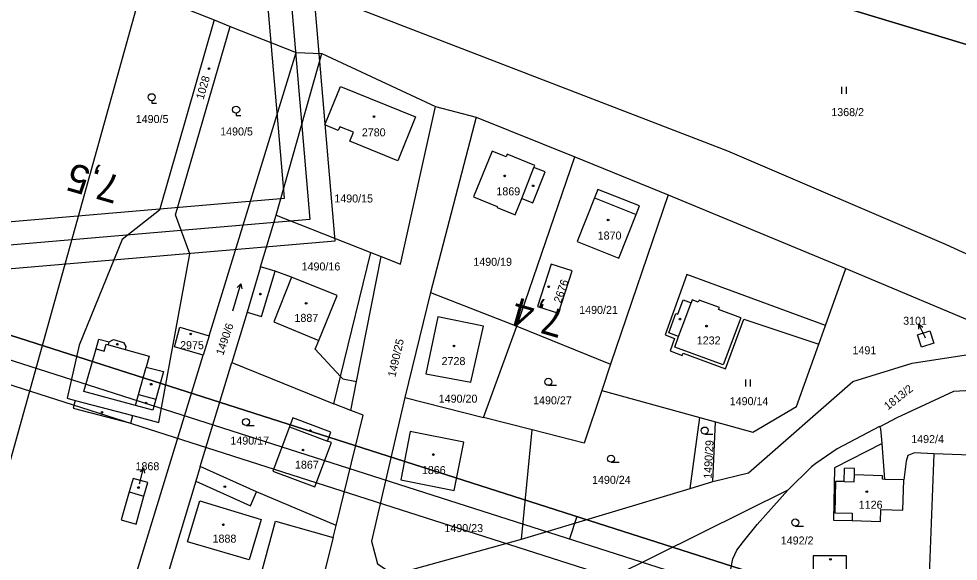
# Model space of a CAD drawing. Extents: x -779330 to -774454, y -1144748 to -1142831.
# Drawn here: x -777612.9 to -777413.3, y -1143849.7 to -1143734.5 of the extents above; entities that cross this region are included whole.
import ezdxf

# ---------------------------------------------------------------- set-up
doc = ezdxf.new("R2010")
doc.units = 0
for name, color, linetype in [('Hranice parcel', 7, 'Continuous'), ('Parcelní čísla', 7, 'Continuous'), ('Pop  PČ popisy', 7, 'Continuous'), ('SŽDC', 7, 'Continuous'), ('Vnitřní kresba', 7, 'Continuous'), ('Vrstva 1', 7, 'Continuous'), ('Vrstva 53', 7, 'Continuous'), ('Vrstva 7', 7, 'Continuous'), ('Značky budov', 7, 'Continuous'), ('Značky kultur', 7, 'Continuous')]:
    doc.layers.add(name, color=color, linetype=linetype)

msp = doc.modelspace()

# ---------------------------------------------------------------- linework, layer by layer
at = {"layer": 'Hranice parcel'}
for p, q in [((-777586.96, -1143728.55), (-777628.63, -1143877.96)), ((-777586.96, -1143728.55), (-777571.45, -1143734.73)), ((-777571.45, -1143734.73), (-777568.02, -1143736.1)), ((-777568.02, -1143736.1), (-777554, -1143741.68)), ((-777572.48, -1143801.82), (-777554, -1143741.68)), ((-777558.25, -1143776.21), (-777548.54, -1143741.84)), ((-777554, -1143741.68), (-777548.54, -1143741.84)), ((-777548.54, -1143741.84), (-777524.39, -1143753.1)), ((-777524.39, -1143753.1), (-777515.73, -1143755.37)), ((-777515.73, -1143755.37), (-777525.48, -1143792.66)), ((-777515.73, -1143755.37), (-777494.83, -1143763.84)), ((-777507.11, -1143799.78), (-777494.83, -1143763.84)), ((-777494.83, -1143763.84), (-777474.95, -1143771.88)), ((-777474.95, -1143771.88), (-777487.19, -1143807.86)), ((-777474.95, -1143771.88), (-777437.2, -1143787.51)), ((-777561.56, -1143787.19), (-777558.25, -1143776.21)), ((-777558.25, -1143776.21), (-777538.11, -1143784.15)), ((-777544.59, -1143810.44), (-777538.11, -1143784.15)), ((-777441.55, -1143799.67), (-777437.2, -1143787.51)), ((-777525.48, -1143792.66), (-777530.89, -1143814.94)), ((-777525.48, -1143792.66), (-777507.11, -1143799.78)), ((-777579.84, -1143804.2), (-777578.68, -1143800.03)), ((-777578.68, -1143800.03), (-777572.48, -1143801.82)), ((-777514.23, -1143819.18), (-777507.11, -1143799.78)), ((-777507.11, -1143799.78), (-777487.19, -1143807.86)), ((-777442.96, -1143803.61), (-777441.55, -1143799.67)), ((-777572.48, -1143801.82), (-777573.74, -1143805.93)), ((-777573.74, -1143805.93), (-777579.84, -1143804.2)), ((-777592.84, -1143868.11), (-777573.74, -1143805.93)), ((-777574.4, -1143829.61), (-777567.68, -1143807.53)), ((-777567.68, -1143807.53), (-777546.02, -1143816.25)), ((-777487.19, -1143807.86), (-777489.08, -1143813.43)), ((-777546.02, -1143816.25), (-777544.59, -1143810.44)), ((-777489.08, -1143813.43), (-777468.25, -1143819.2)), ((-777530.89, -1143814.94), (-777514.23, -1143819.18)), ((-777503.88, -1143821.81), (-777514.23, -1143819.18)), ((-777470.29, -1143834.25), (-777468.25, -1143819.2)), ((-777468.25, -1143819.2), (-777464.88, -1143820.14)), ((-777465.49, -1143832.81), (-777464.88, -1143820.14)), ((-777506.15, -1143845.05), (-777503.88, -1143821.81)), ((-777429.76, -1143821.62), (-777430, -1143821.16)), ((-777429.52, -1143824.74), (-777429.76, -1143821.62)), ((-777418.55, -1143826.88), (-777419.52, -1143852.7)), ((-777408.15, -1143827.26), (-777418.55, -1143826.88)), ((-777506.15, -1143845.05), (-777470.29, -1143834.25)), ((-777470.29, -1143834.25), (-777465.49, -1143832.81)), ((-777449.55, -1143834.59), (-777486.78, -1143853.07)), ((-777546.16, -1143844.71), (-777545.52, -1143842.15)), ((-777533.28, -1143852.53), (-777506.15, -1143845.05))]:
    msp.add_line(p, q, dxfattribs=at)
for points in [[(-777358.14, -1143760.61), (-777362.08, -1143759.74), (-777364.95, -1143754.01), (-777547.63, -1143698.79)], [(-777375.94, -1143800.75), (-777415.86, -1143782.49), (-777462.27, -1143762.62), (-777556.08, -1143726.43)], [(-777571.45, -1143734.73), (-777583.04, -1143775.14), (-777590.98, -1143781.34), (-777600.08, -1143803.81), (-777602.62, -1143815.11), (-777600.92, -1143815.55), (-777601.35, -1143817.2), (-777589.15, -1143820.42), (-777588.69, -1143818.74), (-777583.15, -1143820.25), (-777576.59, -1143784.44), (-777579.64, -1143776.1), (-777568.02, -1143736.1)], [(-777542.62, -1143760.45), (-777541.85, -1143758.59), (-777544.73, -1143757.41), (-777545.07, -1143758.22), (-777547.92, -1143757.03), (-777544.58, -1143748.84), (-777528.63, -1143755.28), (-777532.39, -1143764.63), (-777542.62, -1143760.45)], [(-777538.11, -1143784.15), (-777535.92, -1143785.01), (-777531.8, -1143786.63), (-777524.39, -1143753.1)], [(-777509.41, -1143763.79), (-777512.38, -1143762.59), (-777516.33, -1143772.28), (-777511.29, -1143774.33), (-777511.29, -1143774.58), (-777507.44, -1143776.1), (-777506.08, -1143772.67), (-777503.74, -1143773.61), (-777501.12, -1143767.03), (-777503.49, -1143766.09), (-777503.3, -1143765.62), (-777509.19, -1143763.24), (-777509.41, -1143763.79)], [(-777494.32, -1143781.82), (-777485.45, -1143785.36), (-777481.75, -1143776.05), (-777481.04, -1143774.24), (-777489.89, -1143770.75), (-777490.61, -1143772.54), (-777494.32, -1143781.82)], [(-777561.56, -1143787.19), (-777564.44, -1143796.78), (-777567.68, -1143807.53)], [(-777544.59, -1143810.44), (-777549.94, -1143804.7), (-777549.16, -1143802.8), (-777545.26, -1143793.28), (-777554.99, -1143789.4), (-777558.44, -1143788.13), (-777561.56, -1143787.19)], [(-777498.3, -1143797.05), (-777495.36, -1143788), (-777499.84, -1143786.63), (-777502.7, -1143795.62), (-777498.3, -1143797.05)], [(-777437.2, -1143787.51), (-777405.54, -1143800.83), (-777387.68, -1143807.89)], [(-777441.55, -1143799.67), (-777471.01, -1143788.8), (-777475.63, -1143801.6), (-777473.61, -1143802.41), (-777474.56, -1143805), (-777471.98, -1143806.02), (-777471.78, -1143805.5), (-777462.81, -1143808.82), (-777458.9, -1143798.28), (-777442.96, -1143803.61)], [(-777514.2, -1143799.8), (-777523.92, -1143797.78), (-777526.42, -1143809.9), (-777516.86, -1143811.71), (-777514.2, -1143799.8)], [(-777419.39, -1143800.8), (-777418.56, -1143803.42), (-777421.16, -1143804.21), (-777421.98, -1143801.63), (-777419.39, -1143800.8)], [(-777464.88, -1143820.14), (-777456.98, -1143822.28), (-777447.69, -1143816.85), (-777442.96, -1143803.61)], [(-777465.49, -1143832.81), (-777457.92, -1143830.94), (-777435.72, -1143811.54), (-777423.12, -1143807.62), (-777410.71, -1143805.75), (-777400, -1143806.27), (-777387.68, -1143807.89)], [(-777489.08, -1143813.43), (-777492.83, -1143824.62), (-777503.88, -1143821.81)], [(-777410.51, -1143813.42), (-777414.33, -1143813.66), (-777426.36, -1143819.29), (-777430, -1143821.16)], [(-777545.52, -1143842.15), (-777539.77, -1143818.66), (-777542.4, -1143817.71), (-777546.02, -1143816.25)], [(-777530.89, -1143814.94), (-777537.99, -1143845.48), (-777536.71, -1143850.29), (-777533.28, -1143852.53)], [(-777547.35, -1143824.19), (-777546.65, -1143822.31), (-777554.72, -1143819.29), (-777555.42, -1143821.17), (-777558.97, -1143830.56), (-777550.02, -1143833.94), (-777546.49, -1143824.51), (-777547.35, -1143824.19)], [(-777518.36, -1143824.44), (-777529.79, -1143822.14), (-777531.78, -1143832.46), (-777520.42, -1143834.72), (-777518.36, -1143824.44)], [(-777430, -1143821.16), (-777430.05, -1143821.07), (-777439.06, -1143825.81), (-777443.57, -1143828.99), (-777444.5, -1143829.67), (-777449.55, -1143834.59)], [(-777429.52, -1143824.74), (-777439.62, -1143829.91), (-777439.81, -1143840.98), (-777435.91, -1143841.04), (-777429.86, -1143841.27), (-777429.76, -1143838.71), (-777425.13, -1143838.85), (-777424.9, -1143832.45)], [(-777424.9, -1143832.45), (-777428.95, -1143832.33), (-777429.52, -1143824.74)], [(-777418.55, -1143826.88), (-777422.63, -1143826.67), (-777424.04, -1143827.28), (-777424.38, -1143828.48), (-777424.9, -1143832.45)], [(-777574.4, -1143829.61), (-777575.32, -1143832.68), (-777580.95, -1143851.46)], [(-777545.52, -1143842.15), (-777562.42, -1143835.01), (-777574.4, -1143829.61)], [(-777588.63, -1143832.11), (-777589.47, -1143835), (-777591.16, -1143840.91), (-777588.02, -1143841.81), (-777586.33, -1143835.89), (-777585.51, -1143833.01), (-777588.63, -1143832.11)], [(-777444.18, -1143852.13), (-777461.74, -1143851.77), (-777461.25, -1143849.21), (-777460.37, -1143847.4), (-777458.98, -1143845.51), (-777456.06, -1143841.9), (-777449.55, -1143834.59)], [(-777563.57, -1143860.33), (-777558.4, -1143841.22), (-777546.16, -1143844.71)], [(-777546.16, -1143844.71), (-777548.69, -1143854.82), (-777551.16, -1143857.13)], [(-777437.09, -1143852.27), (-777437.07, -1143848.56), (-777444.17, -1143848.54), (-777444.18, -1143852.13)]]:
    msp.add_lwpolyline(points, dxfattribs=at)
at = {"layer": 'Pop  PČ popisy'}
for p, q in [((-777421.78, -1143799.3), (-777421.79, -1143800.42)), ((-777420.46, -1143802), (-777421.78, -1143799.3)), ((-777421.78, -1143799.3), (-777420.89, -1143799.98)), ((-777420.31, -1143802.32), (-777420.46, -1143802)), ((-777587.17, -1143832.8), (-777586.44, -1143829.89)), ((-777586.44, -1143829.89), (-777587.17, -1143830.74)), ((-777586.44, -1143829.89), (-777586.2, -1143830.98)), ((-777587.29, -1143833.28), (-777587.17, -1143832.8))]:
    msp.add_line(p, q, dxfattribs=at)
at = {"layer": 'SŽDC'}
msp.add_lwpolyline([(-777622.38, -1143677.44), (-777550.6, -1143697.9), (-777547.63, -1143698.79), (-777364.95, -1143754.01), (-777362.08, -1143759.74), (-777358.14, -1143760.61), (-777354.56, -1143760.13), (-777348.72, -1143768.82), (-777340.59, -1143770.61)], dxfattribs=at)
at = {"layer": 'Vnitřní kresba'}
for p, q in [((-777506.08, -1143772.67), (-777503.49, -1143766.09)), ((-777490.61, -1143772.54), (-777481.75, -1143776.05)), ((-777541.16, -1143811.54), (-777535.92, -1143785.01)), ((-777561.33, -1143797.71), (-777558.44, -1143788.13)), ((-777554.99, -1143789.4), (-777558.75, -1143798.87)), ((-777472.93, -1143797.23), (-777471.79, -1143794.16)), ((-777471.79, -1143794.16), (-777470.07, -1143794.8)), ((-777469.84, -1143794.17), (-777470.07, -1143794.8)), ((-777468.56, -1143794.65), (-777469.84, -1143794.17)), ((-777468.4, -1143794.23), (-777468.56, -1143794.65)), ((-777464.08, -1143795.85), (-777468.4, -1143794.23)), ((-777471.21, -1143797.86), (-777470.07, -1143794.8)), ((-777464.24, -1143796.27), (-777464.08, -1143795.85)), ((-777459.56, -1143798.03), (-777464.24, -1143796.27)), ((-777564.44, -1143796.78), (-777561.33, -1143797.71)), ((-777474.81, -1143801.17), (-777473.33, -1143797.08)), ((-777473.33, -1143797.08), (-777472.93, -1143797.23)), ((-777472.78, -1143801.97), (-777471.21, -1143797.86)), ((-777459.56, -1143798.03), (-777463.27, -1143808.03)), ((-777558.75, -1143798.87), (-777549.16, -1143802.8)), ((-777472.78, -1143801.97), (-777474.81, -1143801.17)), ((-777473.56, -1143804.21), (-777472.78, -1143801.97)), ((-777596.52, -1143804.59), (-777595.93, -1143802.51)), ((-777595.93, -1143802.51), (-777593.7, -1143803.14)), ((-777594.8, -1143805.08), (-777594.37, -1143803.58)), ((-777594.37, -1143803.58), (-777593.86, -1143803.72)), ((-777593.86, -1143803.72), (-777593.7, -1143803.14)), ((-777593.86, -1143803.72), (-777590.36, -1143804.71)), ((-777593.7, -1143803.14), (-777592.8, -1143802.58)), ((-777592.8, -1143802.58), (-777590.69, -1143803.25)), ((-777590.69, -1143803.25), (-777590.19, -1143804.11)), ((-777590.19, -1143804.11), (-777590.36, -1143804.71)), ((-777463.27, -1143808.03), (-777473.56, -1143804.21)), ((-777599.1, -1143813.64), (-777596.52, -1143804.59)), ((-777596.52, -1143804.59), (-777594.8, -1143805.08)), ((-777590.36, -1143804.71), (-777585.26, -1143806.15)), ((-777585.26, -1143806.15), (-777585.89, -1143808.48)), ((-777587.48, -1143814.3), (-777585.89, -1143808.48)), ((-777585.89, -1143808.48), (-777582.21, -1143809.43)), ((-777582.21, -1143809.43), (-777583.79, -1143815.29)), ((-777544.59, -1143810.44), (-777544.1, -1143810.96)), ((-777544.1, -1143810.96), (-777541.16, -1143811.54)), ((-777542.4, -1143817.71), (-777541.16, -1143811.54)), ((-777588.12, -1143816.63), (-777599.1, -1143813.64)), ((-777588.12, -1143816.63), (-777587.48, -1143814.3)), ((-777587.48, -1143814.3), (-777583.79, -1143815.29)), ((-777600.92, -1143815.55), (-777588.69, -1143818.74)), ((-777583.79, -1143815.29), (-777584.43, -1143817.64)), ((-777584.43, -1143817.64), (-777588.12, -1143816.63)), ((-777555.42, -1143821.17), (-777547.35, -1143824.19)), ((-777437.6, -1143832.8), (-777437.52, -1143829.97)), ((-777435.35, -1143830.02), (-777437.52, -1143829.97)), ((-777435.38, -1143831.38), (-777435.35, -1143830.02)), ((-777435.42, -1143832.85), (-777435.38, -1143831.38)), ((-777429.42, -1143831.56), (-777435.38, -1143831.38)), ((-777429.45, -1143832.31), (-777429.42, -1143831.56)), ((-777575.32, -1143832.68), (-777563.69, -1143837.94)), ((-777439.39, -1143832.75), (-777439.56, -1143839.47)), ((-777437.6, -1143832.8), (-777439.39, -1143832.75)), ((-777437.6, -1143832.8), (-777435.42, -1143832.85)), ((-777428.95, -1143832.33), (-777429.45, -1143832.31)), ((-777589.47, -1143835), (-777586.33, -1143835.89)), ((-777563.69, -1143837.94), (-777562.42, -1143835.01)), ((-777577.09, -1143845.59), (-777574.47, -1143836.9)), ((-777574.47, -1143836.9), (-777561.45, -1143840.83)), ((-777439.56, -1143839.47), (-777435.91, -1143839.53)), ((-777435.91, -1143839.53), (-777435.91, -1143841.04)), ((-777561.45, -1143840.83), (-777563.99, -1143849.44)), ((-777563.99, -1143849.44), (-777577.09, -1143845.59))]:
    msp.add_line(p, q, dxfattribs=at)
at = {"layer": 'Vrstva 1'}
msp.add_line((-777494.38, -1143840.23), (-777495.91, -1143844.98), dxfattribs=at)
for points in [[(-776606.88, -1143822.95), (-777806.9, -1143438.86), (-777897.43, -1143721.71), (-776697.42, -1144105.81)], [(-776700.65, -1144099.52), (-777891.15, -1143718.47), (-777803.66, -1143445.14), (-776613.17, -1143826.19)], [(-777571, -1143485.76), (-778617.18, -1143575.21), (-778591.88, -1143871.12), (-777545.7, -1143781.67)], [(-777551.11, -1143777.12), (-778587.32, -1143865.71), (-778611.77, -1143579.77), (-777575.56, -1143491.17)], [(-777580.11, -1143496.57), (-778407.09, -1143567.28), (-778383.5, -1143843.27), (-777556.51, -1143772.57)], [(-776619.45, -1143829.42), (-777605.19, -1143513.91), (-777689.63, -1143777.73), (-776703.89, -1144093.24)], [(-776703.89, -1144093.24), (-777689.63, -1143777.73), (-777605.19, -1143513.91), (-776619.45, -1143829.42)]]:
    msp.add_lwpolyline(points, close=True, dxfattribs=at)
at = {"layer": 'Vrstva 53'}
msp.add_lwpolyline([(-777340.59, -1143770.61), (-777348.72, -1143768.82), (-777354.56, -1143760.13), (-777358.14, -1143760.61), (-777362.08, -1143759.74), (-777364.95, -1143754.01), (-777547.63, -1143698.79), (-777550.6, -1143697.9), (-777622.38, -1143677.44)], dxfattribs=at)
msp.add_lwpolyline([(-777340.59, -1143770.61), (-777348.72, -1143768.82), (-777354.56, -1143760.13), (-777358.14, -1143760.61), (-777362.08, -1143759.74), (-777364.95, -1143754.01), (-777547.63, -1143698.79), (-777550.6, -1143697.9), (-777622.38, -1143677.44)], dxfattribs=at)
at = {"layer": 'Značky budov'}
for centre in [(-777572.5, -1143745.07), (-777537.46, -1143755.25), (-777509.71, -1143767.86), (-777503.65, -1143769.97), (-777487.72, -1143777.22), (-777500.34, -1143791.42), (-777561.62, -1143792.97), (-777551.89, -1143794.92), (-777472.46, -1143798.28), (-777466.81, -1143799.78), (-777576.4, -1143801.44), (-777591.99, -1143803.61), (-777520.45, -1143803.99), (-777584.79, -1143812.12), (-777585.9, -1143816.11), (-777595.26, -1143818.07), (-777550.99, -1143821.96), (-777552.53, -1143826.1), (-777524.87, -1143827.05), (-777587.51, -1143834.07), (-777569.15, -1143833.86), (-777432.77, -1143834.93), (-777569.47, -1143841.98), (-777440.49, -1143849.32)]:
    msp.add_circle(centre, 0.175, dxfattribs=at)
at = {"layer": 'Značky kultur'}
for p, q in [((-777438.06, -1143750.45), (-777438.06, -1143748.95)), ((-777437.06, -1143750.45), (-777437.06, -1143748.95)), ((-777584.69, -1143751.9), (-777584.69, -1143752.4)), ((-777584.69, -1143752.4), (-777583.69, -1143752.4)), ((-777566.75, -1143754.54), (-777566.75, -1143755.04)), ((-777566.75, -1143755.04), (-777565.75, -1143755.04)), ((-777567.42, -1143796.53), (-777565.77, -1143790.77)), ((-777565.77, -1143790.77), (-777566.52, -1143791.57)), ((-777565.77, -1143790.77), (-777565.55, -1143791.84)), ((-777458.44, -1143812.62), (-777458.44, -1143811.12)), ((-777457.44, -1143812.62), (-777457.44, -1143811.12)), ((-777500.42, -1143812.35), (-777498.67, -1143812.35)), ((-777564.64, -1143820.89), (-777562.89, -1143820.89)), ((-777467.2, -1143822.71), (-777465.45, -1143822.71)), ((-777487.1, -1143828.69), (-777485.35, -1143828.69)), ((-777447.96, -1143842.24), (-777446.21, -1143842.24))]:
    msp.add_line(p, q, dxfattribs=at)
for centre in [(-777584.69, -1143751.15), (-777566.75, -1143753.79), (-777500.42, -1143811.6), (-777564.64, -1143820.14), (-777467.2, -1143821.96), (-777487.1, -1143827.94), (-777447.96, -1143841.49)]:
    msp.add_circle(centre, 0.75, dxfattribs=at)

# ---------------------------------------------------------------- texts
at = {"layer": 'Parcelní čísla'}
for s, rotation, p in [('1028', 73.8014, (-777573.7, -1143751.76)), ('2676', 71, (-777497.75, -1143795.01)), ('1490/6', 71, (-777569.51, -1143806.09)), ('1490/25', 77, (-777532.93, -1143810.71)), ('1813/2', 38, (-777428.28, -1143817.69)), ('1490/29', 87, (-777465.74, -1143832.24))]:
    msp.add_text(s, height=1.7, rotation=rotation, dxfattribs=at).set_placement(p)
for s, p in [('1368/2', (-777440.31, -1143755.16)), ('1490/5', (-777588.08, -1143756.63)), ('1490/5', (-777570.14, -1143759.27)), ('2780', (-777540.05, -1143759.46)), ('1869', (-777511.46, -1143771.99)), ('1490/15', (-777545.89, -1143773.51)), ('1870', (-777489.94, -1143781.38)), ('1490/16', (-777552.84, -1143787.95)), ('1490/19', (-777516.36, -1143786.96)), ('1490/21', (-777493.87, -1143797.18)), ('1887', (-777554.36, -1143798.87)), ('3101', (-777425.04, -1143799.48)), ('1232', (-777468.89, -1143803.66)), ('2975', (-777578.66, -1143804.67)), ('1491', (-777435.8, -1143805.76)), ('2728', (-777523.1, -1143808.05)), ('1490/20', (-777523.71, -1143816.03)), ('1490/27', (-777503.66, -1143816.39)), ('1490/14', (-777461.89, -1143816.57)), ('1490/17', (-777567.97, -1143824.94)), ('1492/4', (-777423.33, -1143824.62)), ('1868', (-777588.13, -1143830.39)), ('1867', (-777554.25, -1143830.06)), ('1866', (-777527.29, -1143831.2)), ('1490/24', (-777491.14, -1143833.28)), ('1126', (-777434.48, -1143838.56)), ('1490/23', (-777522.51, -1143843.53)), ('1888', (-777571.76, -1143845.76)), ('1492/2', (-777451.04, -1143846.16))]:
    msp.add_text(s, height=1.7, dxfattribs=at).set_placement(p)
at = {"layer": 'Vrstva 7'}
for s, rotation, p in [('7,5', 164.0172, (-777590.88, -1143768.08)), ('7,4', 164.0024, (-777496.42, -1143796.61))]:
    msp.add_text(s, height=6, rotation=rotation, dxfattribs=at).set_placement(p)

doc.saveas('drawing.dxf')
